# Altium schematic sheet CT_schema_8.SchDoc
size 287 x 160 mm
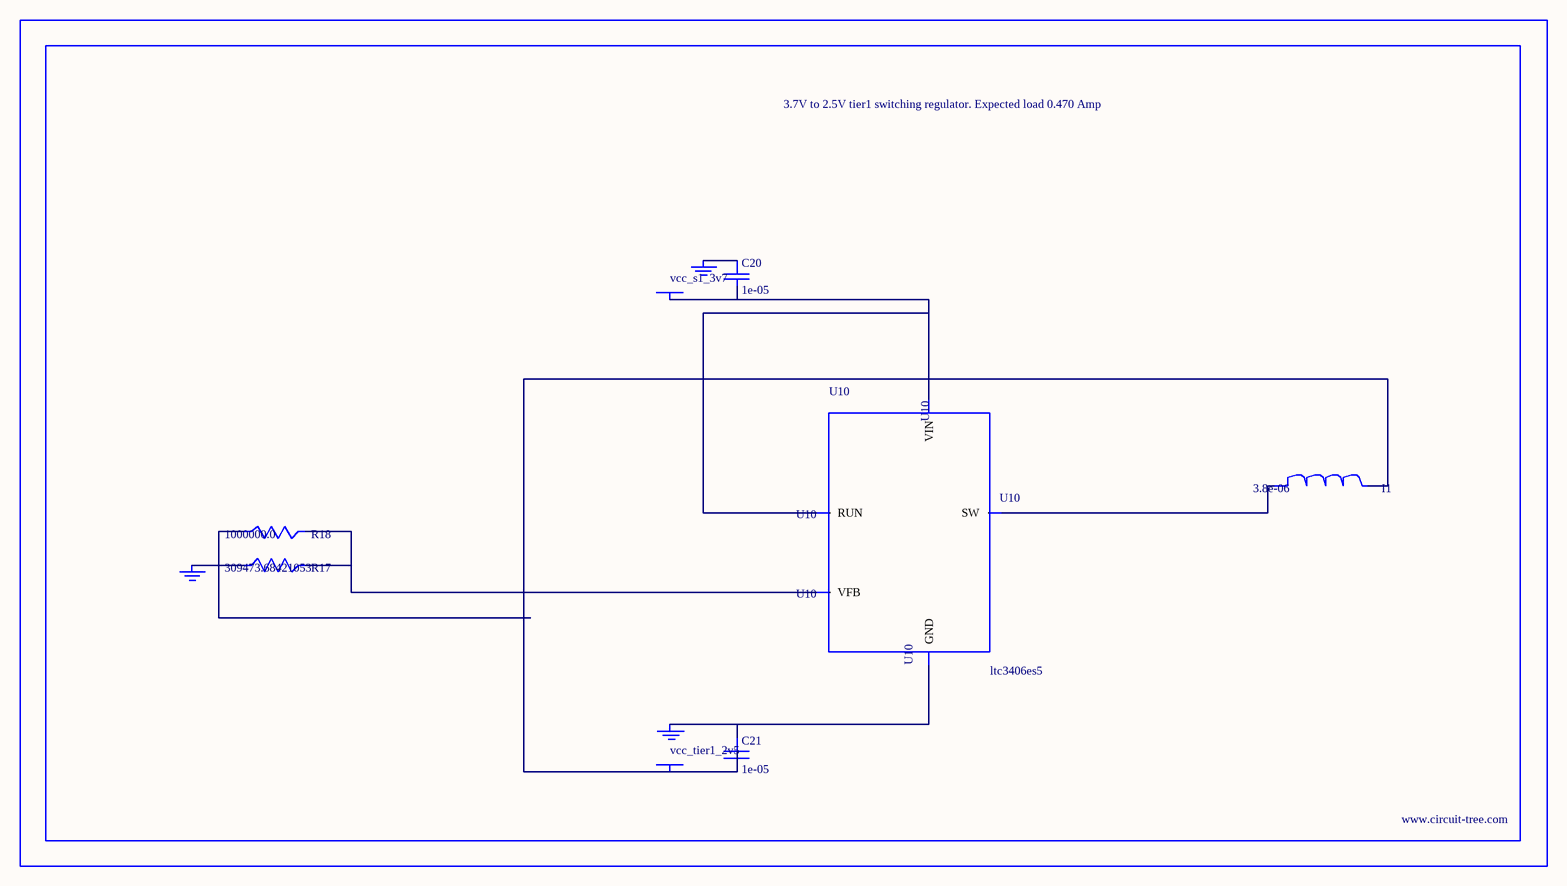
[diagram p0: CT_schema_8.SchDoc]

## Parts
BORDER7  (no value)
C20  1e-05  [C0805]
C21  1e-05  [C0805]
GND_INSTANCE_7_0  (no value)
GND_INSTANCE_7_1  (no value)
GND_INSTANCE_7_2  (no value)
I1  3.8e-06  [DR1040]
POWER_INSTANCE_7_0  vcc_tier1_2v5
POWER_INSTANCE_7_1  vcc_s1_3v7
R17  309473.68421053  [R0603]
R18  1000000.0  [R0603]
U10  ltc3406es5  [TSOT-23-5]

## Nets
NetC20_1: C20.1 GND_INSTANCE_7_1.0(GND)
NetC20_2: C20.2 POWER_INSTANCE_7_1.0(PWR) U10.1(RUN) U10.4(VIN)
NetC21_1: C21.1 GND_INSTANCE_7_0.0(GND) U10.2(GND)
NetC21_2: C21.2 I1.2 POWER_INSTANCE_7_0.0(PWR) R18.1
NetGND_INSTANCE_7_2_0: GND_INSTANCE_7_2.0(GND) R17.1
NetI1_1: I1.1 U10.3(SW)
NetR17_2: R17.2 R18.2 U10.5(VFB)

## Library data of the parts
BORDER7 = BORDER_PAGE7
C20 C21 = C0805C106K8RACTU
GND_INSTANCE_7_0-GND_INSTANCE_7_2 = GND
I1 = DR1040-3R8-R
POWER_INSTANCE_7_0 POWER_INSTANCE_7_1 = PWR
R17 = R17
R18 = RC0603JR-071ML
